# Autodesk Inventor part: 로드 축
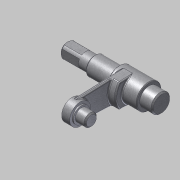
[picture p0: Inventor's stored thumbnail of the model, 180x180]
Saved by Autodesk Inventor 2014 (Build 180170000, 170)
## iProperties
Created: 2015-10
Part Number: 로드 축
Document SubType Name: Modeling
Designer: mdu
Density: 7.86 g/cm^3
Material: 강철, 연강
Mass: 151.797 g
Surface Area: 62.904 cm^2
Volume: 19.3125 cm^3
Appearance: 금속-강(스테인리스, 브러시됨)
Author: mdu
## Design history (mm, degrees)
sketch "스케치1"
  geometry: L1 (-3.325, 13.5)-(-3.325, -13.5) reference; L2 (48.675, -15.7)-(48.675, 15.7) reference; L3 (48.675, 0)-(-26.325, 0); L4 (39.675, -18.06)-(39.675, 18.06) reference; L5 (15.675, 18.855)-(15.675, -18.855) reference; L6 (6.675, 15.7)-(6.675, -15.7) reference; L7 (3.675, -10)-(3.675, 10) reference; L8 (49.675, 7.5)-(39.675, 7.5); L9 (39.675, 7.5)-(39.675, 10); L10 (39.675, 10)-(15.675, 10); L11 (15.675, 10)-(15.675, 7.5); L12 (15.675, 7.5)-(-4.325, 7.5); L13 (-4.325, 7.5)-(-4.325, 6); L14 (-4.325, 6)-(-26.325, 6); L15 (-26.325, 6)-(-26.325, 0); L16 (48.675, 0)-(49.675, 0); L17 (49.675, 0)-(49.675, 7.5); 1 further point
  constraints: 22 end point, 7 perpendicular, 4 point on line, 2 parallel, 1 collinear, 1 midpoint
  dimensions: "d0" = 15 diameter of L8 L3; "d1" = 20 diameter of L10 L3; "d2" = 12 diameter of L14 L3; "d3" = 20 distance of L11.end L12.end; "d4" = 1 distance between parallel lines of L17 L2; "d5" = 75 distance of L3.start L3.end
revolve "회전1" sketch "스케치1" stored, may be unused: angle "d6" = 90 deg
chamfer "모따기1" distance "d7" = 1; stored, may be unused: second distance "d8" = 2, angle "d9" = 45 deg
node "작업 평면1"
sketch "스케치2"
  geometry: 1 further point
sketch "스케치3"
  geometry: L1 (9.993, -0.375)-(8.494, -40.319); L2 (-8.494, -40.319)-(-9.993, -0.375); C1 r 10 at (0, 0) reference; A1 r 8.5 centre (0, -40) between (8.494, -40.319) and (-8.494, -40.319); A2 r 10 centre (0, 0) between (-9.993, -0.375) and (9.993, -0.375) reference; 1 further point
  constraints: 4 end point, 4 point on circle, 4 tangent, 1 centre point, 1 vertical alignment
  dimensions: "d12" = 17 diameter of A1; "d22" = 40 distance of A1.centre A2.centre
  node "투영된 루프1"
extrude "돌출1" join sketch "스케치3" distance "d13" = 6.5; taper "d14" = 0 deg
node "작업 평면3"
  node "작업 평면2"
extrude "돌출2" join sketch "스케치3" stored distance "d17" = 6; taper "d18" = 0 deg
sketch "스케치7"
  geometry: L1 (-9.993, -0.375)-(-8.494, -40.319) reference; L2 (8.494, -40.319)-(9.993, -0.375) reference; A1 r 10 centre (0, 0) between (-9.993, -0.375) and (9.993, -0.375) reference; A2 r 15 centre (0, 0) between (-9.574, -11.547) and (9.574, -11.547); 1 further point
  constraints: 2 point on circle, 2 point on line, 1 centre point, 1 coincident
  dimensions: "d32" = 30 diameter of A2
extrude "돌출6" join sketch "스케치7" distance "d33" = 6; taper "d34" = 0 deg
sketch "스케치5"
  geometry: C1 r 5 at (0, 0) reference; C2 r 6.5 at (0, 0); 1 further point
  constraints: 1 centre point, 1 coincident
  dimensions: "d23" = 13 diameter of C2
  node "참조8"
extrude "돌출4" join sketch "스케치5" distance "d24" = 9; taper "d25" = 0 deg
extrude "돌출5" join sketch "스케치5" distance "d26" = 1; taper "d27" = 0 deg
fillet "모깎기1" dims "d28" = 1
chamfer "모따기2" distance "d29" = 1; stored, may be unused: second distance "d30" = 2, angle "d31" = 45 deg
chamfer "모따기3" distance "d35" = 0.5; stored, may be unused: second distance "d36" = 2, angle "d37" = 45 deg
sketch "스케치8"
  geometry: L1 (-3.25, 5.044)-(3.25, 5.044); L2 (5.044, 3.25)-(5.044, -3.25); L3 (3.25, -5.044)-(-3.25, -5.044); L4 (-5.044, -3.25)-(-5.044, 3.25); 2 further points
  constraints: 8 end point, 6 perpendicular, 1 horizontal, 9 other
  dimensions: "d38" = 6.5 distance of L3.start L3.end
extrude "돌출7" cut sketch "스케치8" distance "d39" = 15; taper "d40" = 0 deg
node "솔리드1"
node "참조1"
node "참조2"
node "참조3"
node "참조4"
node "참조5"
node "참조6"
other parameters: "d10" = -8.5, "d15" = -1, "d16" = -3
